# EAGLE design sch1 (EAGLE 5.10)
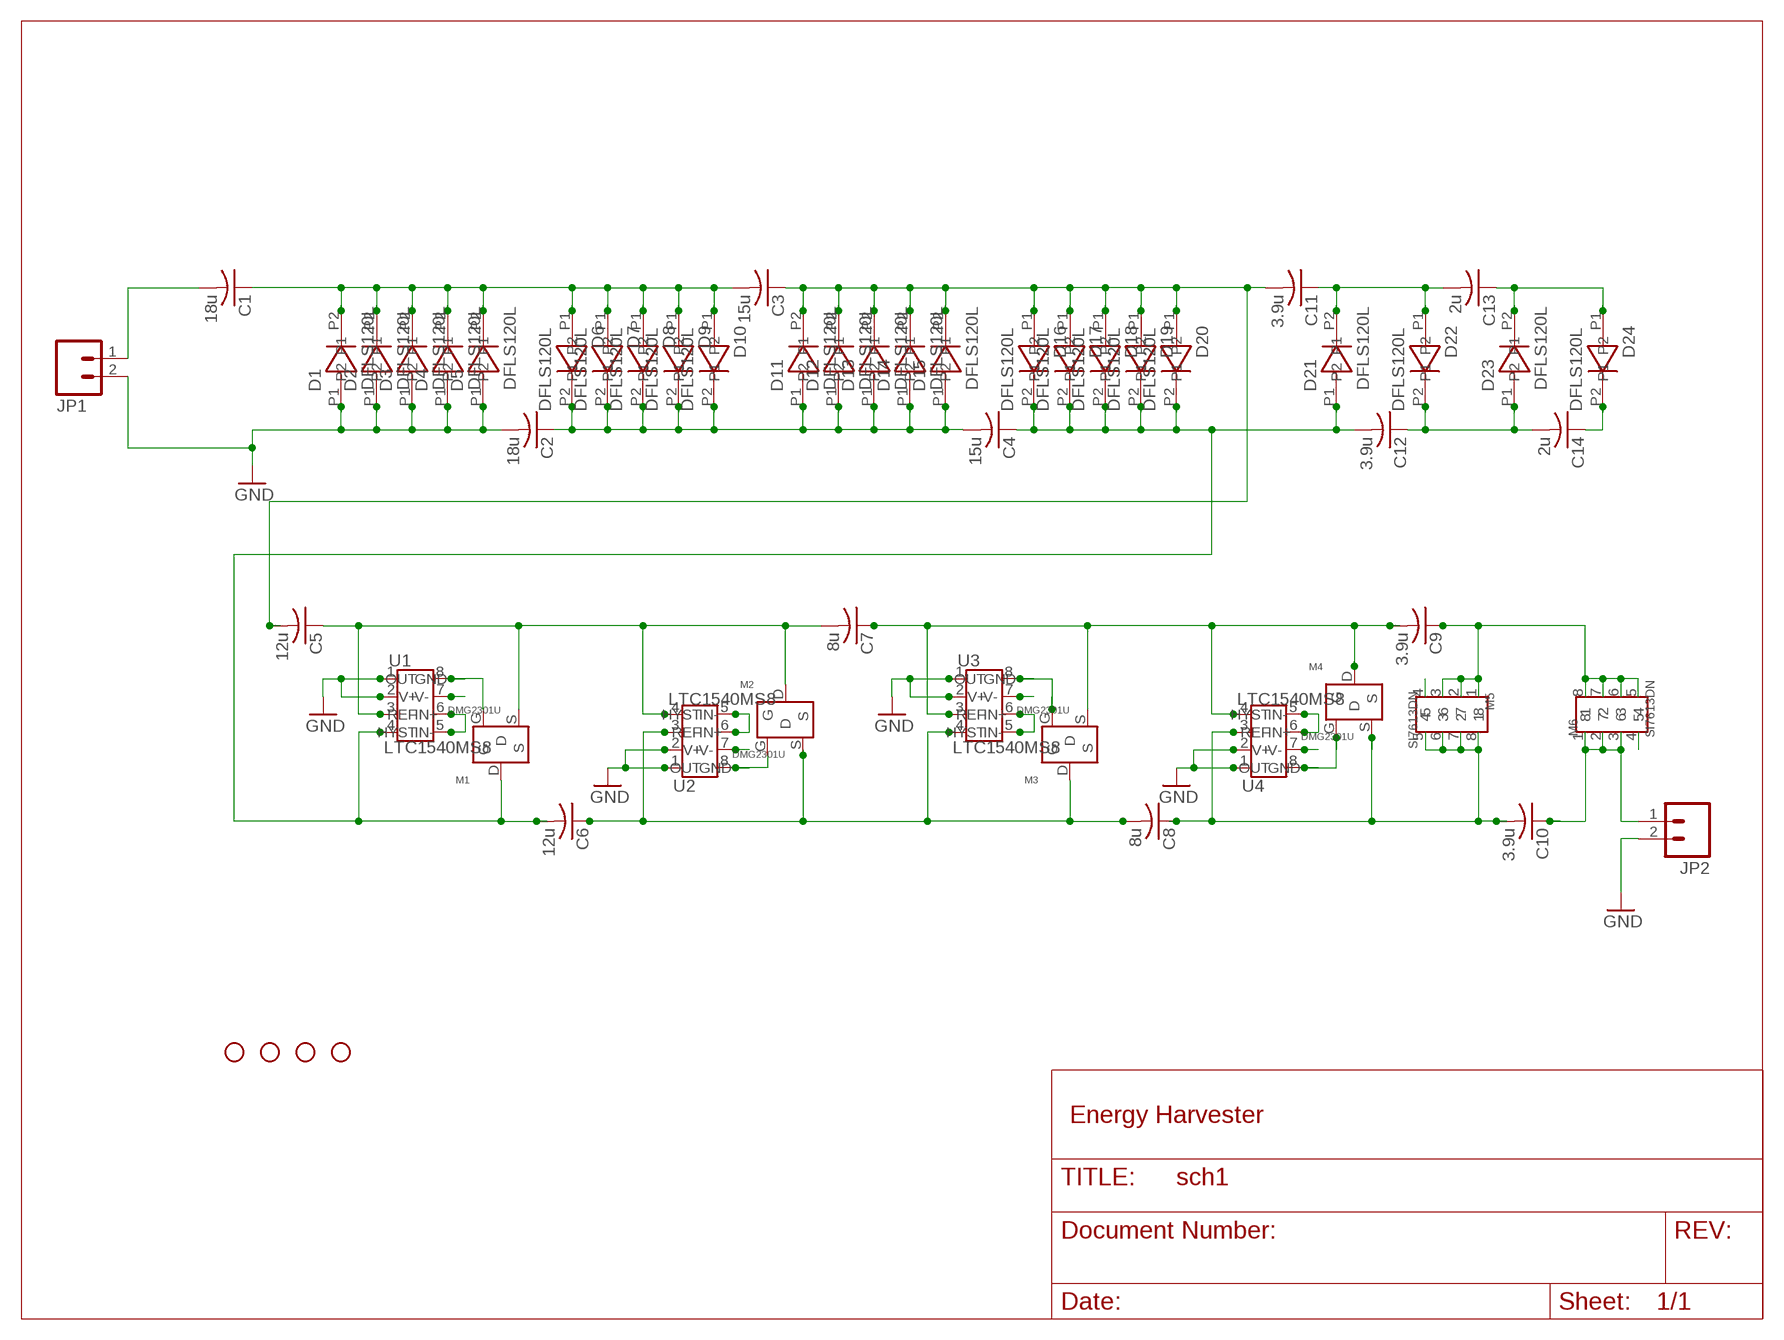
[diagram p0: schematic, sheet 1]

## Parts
C1  18u  C-USC1210  [C1210]
C2  18u  C-USC1210  [C1210]
C3  15u  C-USC1210  [C1210]
C4  15u  C-USC1210  [C1210]
C5  12u  C-USC1210  [C1210]
C6  12u  C-USC1210  [C1210]
C7  8u  C-USC0603  [C0603]
C8  8u  C-USC0603  [C0603]
C9  3.9u  C-USC0603  [C0603]
C10  3.9u  C-USC0603  [C0603]
C11  3.9u  C-USC0603  [C0603]
C12  3.9u  C-USC0603  [C0603]
C13  2u  C-USC0603  [C0603]
C14  2u  C-USC0603  [C0603]
D1  DFLS120L  [POWER_DI]
D2  DFLS120L  [POWER_DI]
D3  DFLS120L  [POWER_DI]
D4  DFLS120L  [POWER_DI]
D5  DFLS120L  [POWER_DI]
D6  DFLS120L  [POWER_DI]
D7  DFLS120L  [POWER_DI]
D8  DFLS120L  [POWER_DI]
D9  DFLS120L  [POWER_DI]
D10  DFLS120L  [POWER_DI]
D11  DFLS120L  [POWER_DI]
D12  DFLS120L  [POWER_DI]
D13  DFLS120L  [POWER_DI]
D14  DFLS120L  [POWER_DI]
D15  DFLS120L  [POWER_DI]
D16  DFLS120L  [POWER_DI]
D17  DFLS120L  [POWER_DI]
D18  DFLS120L  [POWER_DI]
D19  DFLS120L  [POWER_DI]
D20  DFLS120L  [POWER_DI]
D21  DFLS120L  [POWER_DI]
D22  DFLS120L  [POWER_DI]
D23  DFLS120L  [POWER_DI]
D24  DFLS120L  [POWER_DI]
JP1  M02LOCK_LONGPADS  [1X02_LOCK_LONGPADS]
JP2  M02LOCK_LONGPADS  [1X02_LOCK_LONGPADS]
JP3  STAND-OFF  [STAND-OFF]
JP4  STAND-OFF  [STAND-OFF]
JP5  STAND-OFF  [STAND-OFF]
JP6  STAND-OFF  [STAND-OFF]
M1  DMG2301U  [SOT-23]
M2  DMG2301U  [SOT-23]
M3  DMG2301U  [SOT-23]
M4  DMG2301U  [SOT-23]
M5  SI7613DN  [POWERPAK_1212-8]
M6  SI7613DN  [POWERPAK_1212-8]
U1  LTC1540MS8  [MS8]
U2  LTC1540MS8  [MS8]
U3  LTC1540MS8  [MS8]
U4  LTC1540MS8  [MS8]

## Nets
GATE1: M3.G M5.4 U3.8(OUT)
GATE2: M4.G M6.4 U4.8(OUT)
GND: C2.2 D1.P1 D2.P1 D3.P1 D4.P1 D5.P1 JP1.2 JP2.2 U1.1(GND) U1.2(V-) U2.1(GND) U2.2(V-) U3.1(GND) U3.2(V-) U4.1(GND) U4.2(V-)
N$1: C1.1 C3.2 D1.P2 D2.P2 D3.P2 D4.P2 D5.P2 D6.P1 D7.P1 D8.P1 D9.P1 D10.P1
N$2: C2.1 C4.2 D6.P2 D7.P2 D8.P2 D9.P2 D10.P2 D11.P1 D12.P1 D13.P1 D14.P1 D15.P1
N$3: C13.1 D23.P2 D24.P1
N$4: C3.1 C5.2 C11.2 D11.P2 D12.P2 D13.P2 D14.P2 D15.P2 D16.P1 D17.P1 D18.P1 D19.P1 D20.P1
N$5: C4.1 C6.2 C12.2 D16.P2 D17.P2 D18.P2 D19.P2 D20.P2 D21.P1 M1.D U1.4(IN-)
N$6: C11.1 C13.2 D21.P2 D22.P1
N$7: C12.1 C14.2 D22.P2 D23.P1
N$8: C8.1 C10.2 M4.S M5.5 M5.6 M5.7 M5.8 U4.3(IN+)
N$9: C5.1 C7.2 M1.S M2.D U1.3(IN+) U2.4(IN-)
N$10: C9.1 M5.1 M5.2 M5.3 M6.5 M6.6 M6.7 M6.8
N$11: M1.G U1.8(OUT)
N$12: U1.5(HYST) U1.6(REF)
N$13: C10.1 JP2.1 M6.1 M6.2 M6.3
N$14: U3.5(HYST) U3.6(REF)
N$15: C6.1 C8.2 M2.S M3.D U2.3(IN+) U3.4(IN-)
N$16: M2.G U2.8(OUT)
N$17: U2.5(HYST) U2.6(REF)
N$18: C1.2 JP1.1
N$20: U4.5(HYST) U4.6(REF)
N$22: C7.1 C9.2 M3.S M4.D U3.3(IN+) U4.4(IN-)
VDC: C14.1 D24.P2 U1.7(V+) U2.7(V+) U3.7(V+) U4.7(V+)

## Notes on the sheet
- Energy Harvester

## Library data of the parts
C1-C14 = rcl:C-US: CAPACITOR, American symbol
D1-D24 = sam:DFLS120L
JP1 JP2 = SparkFun:M02: Header 2
JP3-JP6 = SparkFun:STAND-OFF: Stand Off
M1-M4 = sam:DMG2301U
M5 M6 = sam:SI7613DN
U1-U4 = sam:LTC1540

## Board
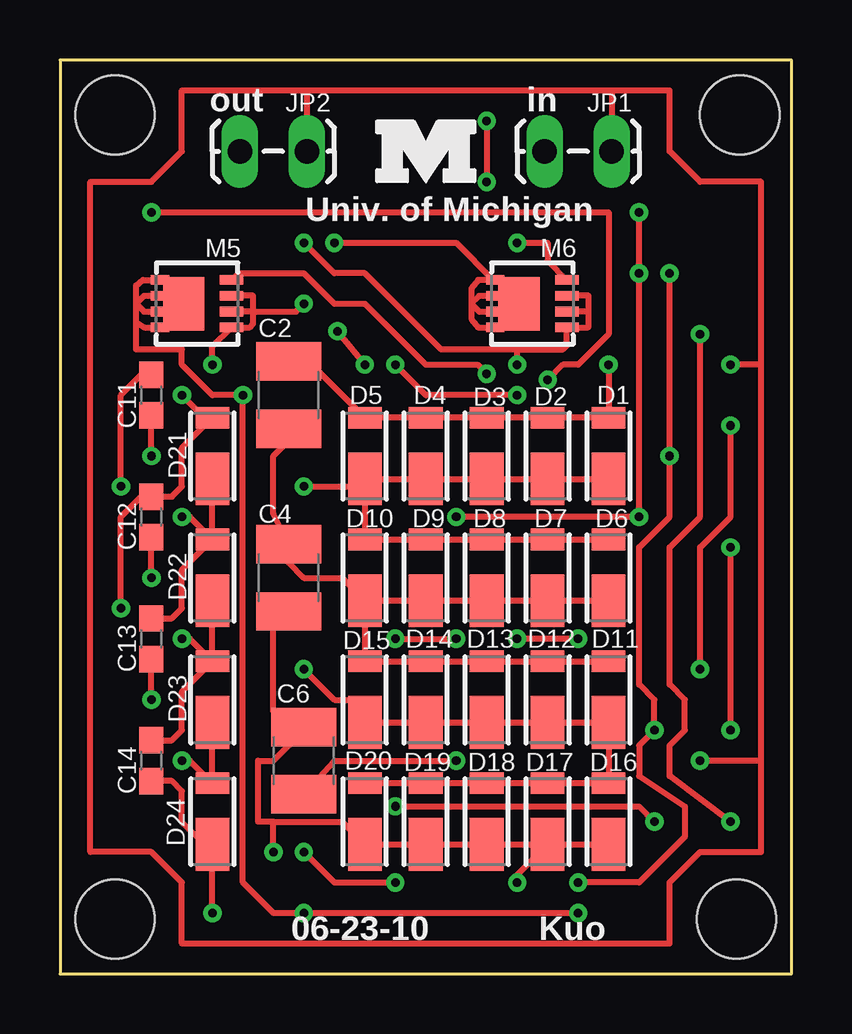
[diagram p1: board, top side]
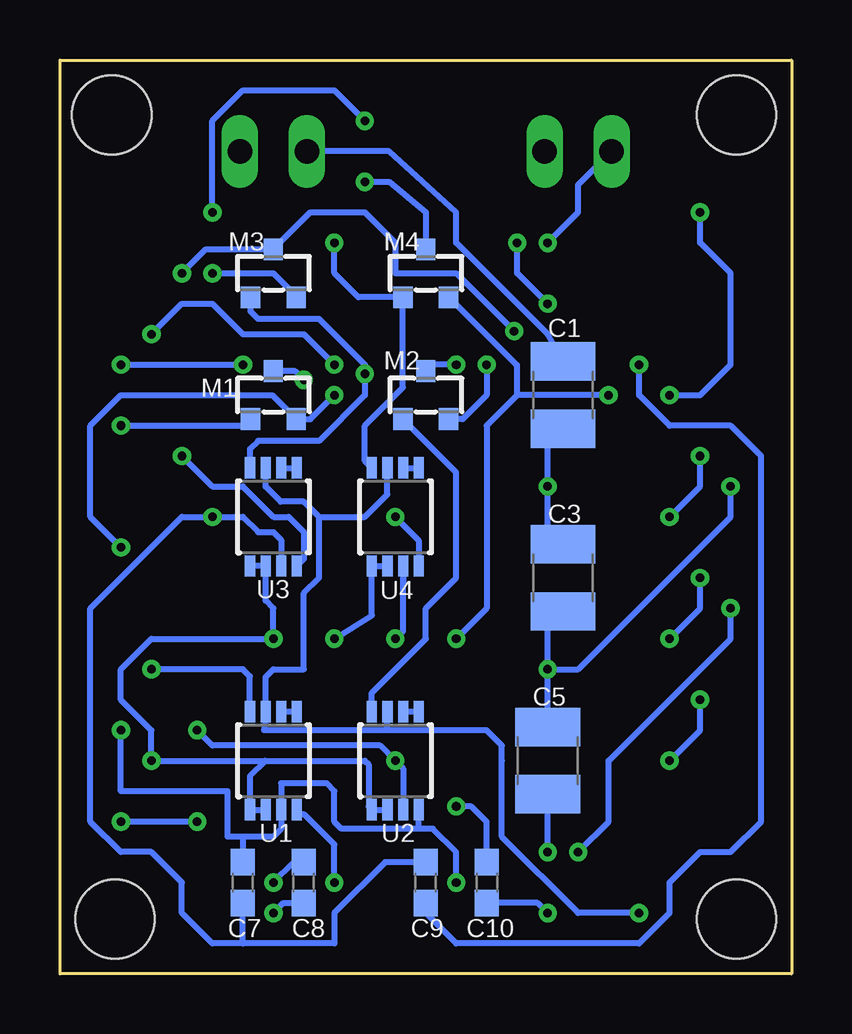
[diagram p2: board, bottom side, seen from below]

Size 30.48 x 38.1 mm. Coordinates in mm from the lower left corner, seen from the top.
Outline: 0,0 30.48,0 30.48,38.1 0,38.09 0,0
Copper layers (1*16): Top 0.0178mm / dielectric 1.4986mm / Bottom 0.0178mm
Design rules "SSC-EAGLE-2Lyr_v1.0.0.3": minimum track width 6mil, minimum drill 14mil, track to track 6mil, track to pad 6mil, pad to pad 6mil, via to via 6mil, smd to smd 6mil, copper to edge 20mil, drill to drill 16mil, minimum pad ring 8mil, minimum via ring 8mil, stop-mask expansion 3mil, vias tented up to drill 0mil, thermal gap 10mil

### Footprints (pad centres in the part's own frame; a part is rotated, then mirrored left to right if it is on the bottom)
C1210 = smd 1.6 x 2.7: 1 -1.4,0; 2 1.4,0
C0603 = smd 1.1 x 1: 1 -0.85,0; 2 0.85,0
POWER_DI = smd 0.9 x 1.4: P1 1.6,0 | smd 2.2 x 1.4: P2 -0.95,0
1X02_LOCK_LONGPADS = drill 1.016 long: 1 -0.127,0; 2 2.667,0
STAND-OFF = hole 3.302: 0,0
SOT-23 = smd 0.8 x 0.9: D 0,1; G -0.95,-1; S 0.95,-1
POWERPAK_1212-8 = smd 0.99 x 0.405: 1 -1.435,0.99; 2 -1.435,0.33; 3 -1.435,-0.33; 4 -1.435,-0.99 | smd 0.76 x 0.405: 5 1.55,-0.99; 6 1.55,-0.33; 7 1.55,0.33; 8 1.55,0.99 | smd 1.725 x 2.235: P$9 0.557,0
MS8 = smd 0.42 x 0.889: 1 -0.975,-2.045; 2 -0.325,-2.045; 3 0.325,-2.045; 4 0.975,-2.045; 5 0.975,2.045; 6 0.325,2.045; 7 -0.325,2.045; 8 -0.975,2.045

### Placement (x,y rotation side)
C1  9.53,24.13 90 bottom
C2  9.53,24.13 90 top
C3  9.53,16.51 90 bottom
C4  9.53,16.51 90 top
C5  10.16,8.89 90 bottom
C6  10.16,8.89 90 top
C7  22.86,3.81 90 bottom
C8  20.32,3.81 90 bottom
C9  15.24,3.81 90 bottom
C10  12.7,3.81 270 bottom
C11  3.81,24.13 90 top
C12  3.81,19.05 90 top
C13  3.81,13.97 90 top
C14  3.81,8.89 90 top
D1  22.86,21.59 90 top
D2  20.32,21.59 90 top
D3  17.78,21.59 90 top
D4  15.24,21.59 90 top
D5  12.7,21.59 90 top
D6  22.86,16.51 90 top
D7  20.32,16.51 90 top
D8  17.78,16.51 90 top
D9  15.24,16.51 90 top
D10  12.7,16.51 90 top
D11  22.86,11.43 90 top
D12  20.32,11.43 90 top
D13  17.78,11.43 90 top
D14  15.24,11.43 90 top
D15  12.7,11.43 90 top
D16  22.86,6.35 90 top
D17  20.32,6.35 90 top
D18  17.78,6.35 90 top
D19  15.24,6.35 90 top
D20  12.7,6.35 90 top
D21  6.35,21.59 90 top
D22  6.35,16.51 90 top
D23  6.35,11.43 90 top
D24  6.35,6.35 90 top
JP1  20.32,34.29 0 top
JP2  7.62,34.29 0 top
JP3  2.29,2.29 0 top
JP4  2.29,35.81 0 top
JP5  28.32,35.81 0 top
JP6  28.19,2.29 0 top
M1  21.59,24.13 0 bottom
M2  15.24,24.13 0 bottom
M3  21.59,29.21 0 bottom
M4  15.24,29.21 0 bottom
M5  5.71,27.94 180 top
M6  19.68,27.94 180 top
U1  21.59,8.89 0 bottom
U2  16.51,8.89 0 bottom
U3  21.59,19.05 0 bottom
U4  16.51,19.05 0 bottom

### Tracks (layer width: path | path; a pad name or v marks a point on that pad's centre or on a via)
GATE1  (via drill 0.36)
  Top 0.254: M5.4 7.43,29.21 10.16,29.21 11.43,27.94 12.7,27.94 15.24,25.4 17.4,25.4 v17.78,25.02
  Bottom 0.254: M3.G 22.54,27.62 22.23,27.3 19.68,27.3 17.78,25.4 v17.78,25.02 17.78,24.13 19.68,22.23 22.23,22.23 22.57,21.89 U3.8
GATE2  (via drill 0.36)
  Top 0.254: v19.05,30.48 20.32,30.48 20.32,29.73 M6.4
  Bottom 0.254: U4.8 17.78,21.39 17.78,22.86 16.19,24.45 M4.G 18.05,28.21 19.05,29.21 v19.05,30.48
GND  (via drill 0.36)
  Top 0.254: 29.21,8.89 29.21,5.08 26.67,5.08 25.4,3.81 25.4,1.27 5.08,1.27 5.08,3.81 3.81,5.08 1.27,5.08 1.27,33.02 3.81,33.02 5.08,34.29 5.08,36.83 10.16,36.83 | 29.21,8.89 29.21,25.4 | 29.21,25.4 29.21,33.02 26.67,33.02 25.4,34.29 25.4,36.83 22.86,36.83 | 29.21,8.89 v26.67,8.89 | v21.59,13.97 v19.05,13.97 | v22.86,25.4 D1.P1 D2.P1 D3.P1 D4.P1 D5.P1 10.36,25.53 C2.2 | 29.21,25.4 v27.94,25.4 | 10.16,36.83 22.86,36.83 | JP2.2 10.29,36.7 10.16,36.83 | JP1.2 22.99,36.7 22.86,36.83
  Bottom 0.254: U3.1 U3.2 21.91,15.56 21.59,15.24 v21.59,13.97 26.67,13.97 27.94,12.7 27.94,11.43 26.67,10.16 v26.67,8.89 21.93,8.89 | U2.2 U2.1 17.62,6.99 17.62,8.73 17.78,8.89 21.93,8.89 | U1.2 U1.1 22.57,8.26 21.93,8.89 | U4.2 U4.1 17.48,14.95 v19.05,13.97 | v27.94,25.4 v22.86,25.4
N$1  (via drill 0.36)
  Top 0.254: D5.P2 D4.P2 D3.P2 D2.P2 D1.P2 | D6.P1 D7.P1 D8.P1 D9.P1 D10.P1 | D5.P2 D10.P1 | D10.P1 12.37,18.11 | v10.16,20.32 12.38,20.32 D5.P2
  Bottom 0.254: C1.1 10.16,22.09 v10.16,20.32 10.16,18.55 C3.2
N$2
  Top 0.254: D10.P2 D9.P2 D8.P2 D7.P2 D6.P2 | D11.P1 D12.P1 D13.P1 D14.P1 D15.P1 D10.P2 | 10.29,22.73 C2.1 10.03,22.73 8.89,21.59 8.89,19.18 C4.2 9.53,17.14 10.16,16.51 11.75,16.51 D10.P2
N$3  (via drill 0.36)
  Top 0.254: D23.P2 D24.P1 5.41,8.89 v5.08,8.89 | v3.81,11.43 C13.1
  Bottom 0.254: v3.81,11.43 3.81,10.16 v5.08,8.89
N$4  (via drill 0.36)
  Top 0.254: D20.P1 D19.P1 D18.P1 D17.P1 D16.P1 | D16.P1 22.86,7.62 | v2.54,20.32 2.54,24.13 3.39,24.98 C11.2 | D15.P2 D14.P2 D13.P2 D12.P2 D11.P2 D16.P1 | D15.P2 12.38,10.48 | D15.P2 12.7,11.43 11.43,11.43 v10.16,12.7
  Bottom 0.254: v2.54,20.32 2.54,19.05 8.89,12.7 v10.16,12.7 | v10.16,12.7 10.16,14.47 C3.1 | C5.2 v10.16,12.7
N$5  (via drill 0.36)
  Top 0.254: v5.08,24.13 6.02,23.19 D21.P1 5.08,21.92 5.08,20.32 4.66,19.9 C12.2 3.39,19.9 2.54,19.05 v2.54,15.24 | v3.81,31.75 22.86,31.75 22.86,26.67 21.59,25.4 20.95,25.4 v20.32,24.77 | D17.P2 D16.P2 | D17.P2 D18.P2 D19.P2 D20.P2 11.75,6.35 8.89,6.35 | C4.1 10.16,14.47 | C4.1 9.53,14.61 | C4.1 8.89,14.47 8.89,10.93 C6.2 10.16,10.16 8.89,8.89 8.26,8.89 8.26,6.35 8.89,6.35 | v19.05,3.81 19.05,4.13 D17.P2 | v8.89,5.08 8.89,6.35
  Bottom 0.254: v5.08,24.13 3.81,24.13 2.54,25.4 2.54,29.21 3.81,30.48 v3.81,31.75 | U1.4 20.61,6.64 20.3,6.64 19.05,5.4 v19.05,3.81 | v2.54,15.24 2.54,13.97 7.62,8.89 7.62,6.35 v8.89,5.08 | M1.D 20.68,25.13 v20.32,24.77
N$6  (via drill 0.36)
  Top 0.254: D22.P1 D21.P2 | D22.P1 5.08,16.84 5.08,15.24 4.66,14.82 C13.2 | v5.08,19.05 5.41,19.05 D22.P1 | v3.81,21.59 C11.1
  Bottom 0.254: v3.81,21.59 3.81,20.32 v5.08,19.05
N$7  (via drill 0.36)
  Top 0.254: D23.P1 5.08,11.76 5.08,10.16 4.66,9.74 C14.2 | D23.P1 D22.P2 | v5.08,13.97 5.41,13.97 D23.P1 | v3.81,16.51 C12.1
  Bottom 0.254: v3.81,16.51 3.81,15.24 v5.08,13.97
N$8  (via drill 0.36)
  Top 0.254: v13.97,13.97 v16.51,13.97 | v21.59,2.54 v10.16,2.54 8.89,2.54 7.62,3.81 v7.62,24.13 6.35,24.13 5.08,25.4 5.08,26.04 3.17,26.04 3.17,27.18 | M5.5 3.46,28.93 3.17,28.7 3.17,27.94 | M5.8 3.53,26.95 3.17,27.18 | 3.17,27.18 3.17,27.94 | M5.6 3.5,28.27 3.17,27.94 | M5.7 3.5,27.61 3.17,27.94
  Bottom 0.254: 16.18,16.18 U4.3 16.18,14.29 v16.51,13.97 | v13.97,13.97 12.7,15.24 12.7,22.86 11.43,24.13 | 11.43,24.13 11.43,25.4 11.48,25.4 M4.S | v7.62,24.13 11.43,24.13 | v10.16,2.54 10.58,2.96 C10.2 | C8.1 21.17,2.96 v21.59,2.54
N$9  (via drill 0.36)
  Top 0.254: v27.94,10.16 v27.94,17.78 | v19.05,24.13 15.24,24.13 v13.97,25.4 | v10.16,5.08 11.43,3.81 v13.97,3.81
  Bottom 0.254: v27.94,17.78 29.21,19.05 29.21,22.86 27.94,24.13 21.64,24.13 M1.S 20.05,23.13 v19.05,24.13 | 15.54,6.05 U2.4 | 22.86,5.71 21.59,5.71 21.27,6.04 U1.3 21.27,7.95 19.38,7.95 19.05,7.62 19.05,6.35 18.75,6.05 15.54,6.05 | 22.86,5.71 23.5,5.71 23.5,7.62 27.94,7.62 v27.94,10.16 | v13.97,25.4 14.97,25.4 M2.D | v13.97,3.81 13.97,5.08 14.95,6.05 15.54,6.05 | v10.16,5.08 C5.1 | 22.86,5.71 C7.2
N$10  (via drill 0.36)
  Top 0.254: v10.16,27.94 9.83,27.61 8.05,27.61 | v6.35,25.4 6.35,26.15 M5.1 7.9,26.95 8.05,27.1 8.05,27.61 | v11.43,30.48 16.51,30.48 18.06,28.93 M6.5 17.43,28.93 17.14,28.57 17.14,27.94 | M6.6 17.45,28.27 17.45,28.25 17.14,27.94 | M6.8 17.43,26.95 17.14,27.3 17.14,27.94 | M6.7 17.48,27.61 17.14,27.94 | 8.05,27.61 M5.2 | M5.3 8.05,28.27 8.05,27.61
  Bottom 0.254: v6.35,25.4 6.35,24.13 5.08,22.86 2.54,22.86 1.27,21.59 1.27,6.35 2.54,5.08 3.81,5.08 5.08,3.81 5.08,2.54 6.35,1.27 13.97,1.27 15.24,2.54 C9.1 | v11.43,30.48 11.43,29.21 v10.16,27.94
N$11  (via drill 0.36)
  Top 0.254: v26.67,12.7 26.67,17.78 27.94,19.05 v27.94,22.86
  Bottom 0.254: M1.G 22.81,22.86 v27.94,22.86 | U1.8 22.57,12.4 22.86,12.7 v26.67,12.7
N$12
  Bottom 0.254: U1.6 U1.5
N$13  (via drill 0.36)
  Top 0.254: v26.67,26.67 26.67,19.05 25.4,17.78 25.4,12.06 26.04,11.43 26.04,10.16 25.4,9.53 25.4,8.26 v27.94,6.35 | v10.16,30.48 11.43,29.21 12.7,29.21 15.88,26.04 19.05,26.04 | v13.97,6.99 24.13,6.99 v24.77,6.35 | 19.05,26.04 20.95,26.04 21.12,26.2 M6.1 22,26.95 22.02,26.98 22.02,27.61 | v19.05,25.4 19.05,26.04 | M6.3 22.02,28.27 22.02,27.61 | 22.02,27.61 M6.2
  Bottom 0.254: v19.05,25.4 20.32,26.67 22.86,26.67 24.13,27.94 25.4,27.94 v26.67,26.67 | JP2.1 8.89,32.89 8.89,31.75 v10.16,30.48 | v24.77,6.35 v27.94,6.35 | v13.97,6.99 13.34,6.99 12.7,6.35 C10.1
N$14
  Bottom 0.254: U3.6 U3.5
N$15  (via drill 0.36)
  Top 0.254: v25.4,29.21 v25.4,21.59 25.4,19.05 24.13,17.78 24.13,12.06 24.77,11.43 v24.77,10.16 24.13,9.53 24.13,8.26 26.04,6.99 26.04,5.71 24.13,3.81 v21.59,3.81 | v11.56,26.8 v12.7,25.4 | v16.51,8.89 11.43,8.89 C6.1
  Bottom 0.254: 14.29,23.18 M2.S 13.7,23.13 12.7,24.13 v12.7,25.4 | v25.4,21.59 24.13,20.32 22.86,20.32 21.59,19.05 20.95,19.05 20.32,18.41 20.32,17.3 U3.4 | v25.4,29.21 24.4,30.21 M3.D 20.05,31.75 17.78,31.75 16.51,30.48 16.51,29.21 13.97,29.21 v11.56,26.8 | v21.59,3.81 20.74,4.66 C8.2 | v24.77,10.16 24.13,9.53 17.14,9.53 v16.51,8.89 16.18,8.56 U2.3
N$16
  Bottom 0.254: 16.46,22.86 M2.G 13.97,20.91 13.97,16.51 15.24,15.24 15.24,13.97 17.48,11.72 U2.8
N$17
  Bottom 0.254: U2.6 U2.5
N$18
  Bottom 0.254: JP1.1 16.76,34.29 13.97,31.75 13.97,30.48 10.16,26.67 C1.2
N$20
  Bottom 0.254: U4.6 U4.5
N$22  (via drill 0.36)
  Top 0.254: v16.51,19.05 v24.13,19.05 v24.13,29.21 v24.13,31.75 | v17.78,35.56 v17.78,33.02
  Bottom 0.254: 22.86,1.27 19.05,1.27 19.05,2.54 16.93,4.66 C9.2 | 22.86,1.27 24.13,1.27 25.4,2.54 25.4,3.81 26.67,5.08 27.94,5.08 29.21,6.35 29.21,15.24 25.4,19.05 v24.13,19.05 22.86,19.05 22.23,18.41 21.59,18.41 21.27,18.09 U3.3 | U4.4 15.54,18.07 v16.51,19.05 | M3.S 20.64,28.26 21.59,29.21 v24.13,29.21 | v17.78,33.02 16.76,33.02 15.24,31.75 M4.D | v17.78,35.56 19.05,36.83 22.86,36.83 24.13,35.56 v24.13,31.75 | 22.86,1.27 C7.1
VDC  (via drill 0.36)
  Top 0.254: 6.35,5.08 6.03,5.08 6.03,5.4 | D24.P2 6.35,6.35 | D24.P2 6.03,5.4 | 6.03,5.4 5.08,6.35 5.08,7.62 4.66,8.04 C14.1 | D24.P2 6.67,5.08 | v6.35,2.54 D24.P2
  Bottom 0.254: 16.84,10.16 U2.7 | 16.84,10.16 12.7,10.16 12.06,9.53 12.06,8.89 12.06,5.71 8.89,2.54 v6.35,2.54 | 19.68,19.05 19.68,16.51 20.32,15.88 20.32,12.7 21.59,12.7 21.91,12.38 U1.7 21.91,10.48 21.97,10.16 16.84,10.16 | 19.68,19.05 20.32,19.68 21.28,19.68 21.91,20.32 U3.7 | 19.68,19.05 17.78,19.05 16.84,20 U4.7

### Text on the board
tPlace: out | in | Univ. of Michigan | 06-23-10 | Kuo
